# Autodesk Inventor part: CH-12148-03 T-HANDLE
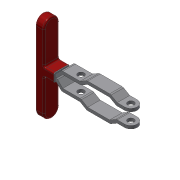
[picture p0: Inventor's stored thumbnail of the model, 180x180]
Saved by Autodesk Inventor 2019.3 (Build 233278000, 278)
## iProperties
Created: 2012-09
Part Number: CH-12148-03 T-HANDLE
Material: Ogólny
Document SubType Name: Modeling
Designer: CADENGINEERING4
Density: 1 g/cm^3
Appearance: Domyślna
Author: CADENGINEERING4
Revision Number: ÈÎºÎ
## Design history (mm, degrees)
feature "Ô²½Ç3"
node "Bryła1"
